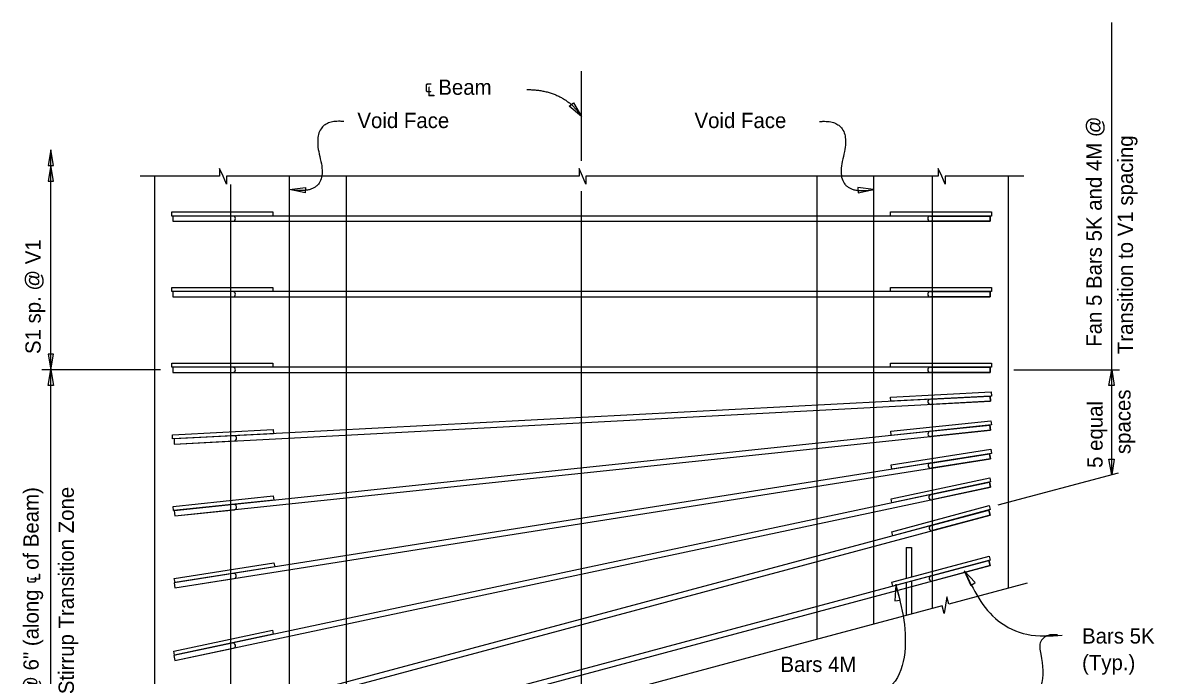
# Model space of a CAD drawing. Extents: x 0.8 to 30.4, y 0.3 to 18.9.
# Drawn here: x 19.16 to 30.38, y 12.43 to 18.91 of the extents above; entities that cross this region are included whole.
import ezdxf

# ---------------------------------------------------------------- set-up
doc = ezdxf.new("R2010")
doc.units = 0
for name, color, linetype in [('BeamConc', 7, 'Continuous'), ('BeamConc_h', 7, 'Continuous'), ('CL_Major', 7, 'Continuous'), ('Dimension', 7, 'Continuous'), ('Rebar', 7, 'Continuous'), ('Rebar_h', 7, 'Continuous'), ('TextStructures', 7, 'Continuous')]:
    doc.layers.add(name, color=color, linetype=linetype)

msp = doc.modelspace()

# ---------------------------------------------------------------- linework, layer by layer
at = {"layer": 'BeamConc'}
for p, q in [((20.473, 11.032), (20.473, 17.385)), ((21.807, 11.389), (21.807, 17.385)), ((27.598, 17.385), (27.598, 12.947)), ((28.932, 17.385), (28.932, 13.298))]:
    msp.add_line(p, q, dxfattribs=at)
at = {"layer": 'BeamConc_h'}
for p, q in [((21.223, 17.303), (21.223, 11.233)), ((22.369, 17.385), (22.369, 11.54)), ((27.036, 17.385), (27.036, 12.79)), ((28.182, 13.097), (28.182, 17.385))]:
    msp.add_line(p, q, dxfattribs=at)
at = {"layer": 'CL_Major'}
for p, q in [((24.702, 17.537), (24.702, 18.427)), ((24.702, 12.302), (24.702, 17.235))]:
    msp.add_line(p, q, dxfattribs=at)
at = {"layer": 'Dimension'}
for p, q in [((29.958, 14.423), (29.958, 18.908)), ((20.527, 15.464), (19.35, 15.464)), ((28.989, 15.464), (30.034, 15.464)), ((30.022, 14.441), (28.83, 14.121))]:
    msp.add_line(p, q, dxfattribs=at)
for points in [[(24.702, 17.978), (24.581, 18.08), (24.621, 18.114)], [(19.442, 17.646), (19.415, 17.49), (19.468, 17.49)], [(19.442, 17.49), (19.415, 17.334), (19.468, 17.334)], [(21.807, 17.252), (21.964, 17.274), (21.962, 17.221)], [(27.598, 17.252), (27.441, 17.274), (27.443, 17.221)], [(19.442, 15.464), (19.468, 15.62), (19.415, 15.62)], [(19.442, 15.464), (19.468, 15.308), (19.415, 15.308)], [(29.958, 15.464), (29.984, 15.308), (29.931, 15.308)], [(29.958, 14.423), (29.931, 14.58), (29.984, 14.58)], [(28.496, 13.47), (28.562, 13.326), (28.606, 13.356)], [(27.817, 13.333), (27.809, 13.175), (27.861, 13.181)]]:
    msp.add_lwpolyline(points, close=True, dxfattribs=at)
for points in [[(19.442, 11.509), (19.442, 17.646)], [(21.694, 17.385), (21.182, 17.385), (21.182, 17.307), (21.148, 17.385), (21.114, 17.462), (21.114, 17.385), (20.325, 17.385)], [(27.522, 17.385), (24.746, 17.385), (24.746, 17.307), (24.712, 17.385), (24.678, 17.462), (24.678, 17.385), (21.694, 17.385)], [(29.086, 17.385), (28.307, 17.385), (28.307, 17.307), (28.273, 17.385), (28.239, 17.462), (28.239, 17.385), (27.522, 17.385)], [(29.121, 13.349), (28.342, 13.141), (28.322, 13.215), (28.31, 13.132), (28.297, 13.048), (28.277, 13.123), (26.782, 12.723)], [(26.782, 12.723), (24.745, 12.177), (24.725, 12.252), (24.713, 12.168), (24.705, 12.116)]]:
    msp.add_lwpolyline(points, dxfattribs=at)
for points in [[(24.159, 18.244), (24.523, 18.244), (24.702, 17.979)], [(22.345, 17.927), (22.008, 17.958), (22.211, 17.182), (21.807, 17.252)], [(27.06, 17.927), (27.397, 17.958), (27.194, 17.182), (27.598, 17.252)]]:
    msp.add_open_spline(points, degree=2, dxfattribs=at)
for points in [[(28.496, 13.47), (28.833, 12.976), (29.118, 12.842), (29.467, 12.833)], [(27.817, 13.338), (27.899, 12.616), (27.755, 12.319), (27.582, 12.253), (27.422, 12.253)], [(29.419, 12.835), (29.343, 12.835), (29.255, 12.772), (29.255, 12.645), (29.255, 12.328), (29.157, 12.174), (29.014, 12.076), (28.873, 12.034), (28.735, 11.996)]]:
    msp.add_spline(points, degree=3, dxfattribs=at)
at = {"layer": 'Rebar'}
for p, q in [((20.64, 17.032), (21.64, 17.032)), ((20.64, 16.99), (20.64, 17.032)), ((21.64, 16.99), (20.64, 16.99)), ((21.245, 16.99), (20.651, 16.99)), ((20.651, 16.99), (20.651, 16.938)), ((21.64, 17.032), (21.64, 16.99)), ((27.765, 17.032), (28.765, 17.032)), ((27.765, 16.99), (27.765, 17.032)), ((28.765, 16.99), (27.765, 16.99)), ((28.16, 16.99), (28.754, 16.99)), ((28.754, 16.99), (28.754, 16.938)), ((28.765, 17.032), (28.765, 16.99)), ((20.651, 16.938), (21.245, 16.938)), ((28.754, 16.938), (28.16, 16.938)), ((20.64, 16.282), (21.64, 16.282)), ((20.64, 16.24), (20.64, 16.282)), ((21.64, 16.282), (21.64, 16.24)), ((27.765, 16.282), (28.765, 16.282)), ((27.765, 16.24), (27.765, 16.282)), ((28.765, 16.282), (28.765, 16.24)), ((21.64, 16.24), (20.64, 16.24)), ((21.245, 16.24), (20.651, 16.24)), ((20.651, 16.24), (20.651, 16.188)), ((20.651, 16.188), (21.245, 16.188)), ((28.765, 16.24), (27.765, 16.24)), ((28.16, 16.24), (28.754, 16.24)), ((28.754, 16.188), (28.16, 16.188)), ((28.754, 16.24), (28.754, 16.188)), ((20.64, 15.532), (21.64, 15.532)), ((20.64, 15.49), (20.64, 15.532)), ((21.64, 15.49), (20.64, 15.49)), ((21.245, 15.49), (20.651, 15.49)), ((20.651, 15.49), (20.651, 15.438)), ((21.64, 15.532), (21.64, 15.49)), ((27.765, 15.532), (28.765, 15.532)), ((27.765, 15.49), (27.765, 15.532)), ((28.765, 15.49), (27.765, 15.49)), ((28.16, 15.49), (28.754, 15.49)), ((28.754, 15.49), (28.754, 15.438)), ((28.765, 15.532), (28.765, 15.49)), ((20.651, 15.438), (21.245, 15.438)), ((28.754, 15.438), (28.16, 15.438)), ((27.765, 15.195), (28.764, 15.247)), ((27.767, 15.153), (27.765, 15.195)), ((28.766, 15.205), (27.767, 15.153)), ((28.16, 15.174), (28.753, 15.205)), ((28.756, 15.153), (28.163, 15.122)), ((28.753, 15.205), (28.756, 15.153)), ((28.764, 15.247), (28.766, 15.205)), ((27.767, 14.856), (28.761, 14.96)), ((28.761, 14.96), (28.766, 14.919)), ((20.646, 14.821), (21.645, 14.873)), ((20.648, 14.779), (20.646, 14.821)), ((21.647, 14.831), (20.648, 14.779)), ((21.256, 14.811), (20.663, 14.78)), ((21.645, 14.873), (21.647, 14.831)), ((27.771, 14.814), (27.767, 14.856)), ((28.766, 14.919), (27.771, 14.814)), ((28.159, 14.855), (28.75, 14.917)), ((28.755, 14.865), (28.165, 14.803)), ((28.75, 14.917), (28.755, 14.865)), ((20.663, 14.78), (20.665, 14.728)), ((20.665, 14.728), (21.259, 14.759)), ((27.771, 14.521), (28.759, 14.677)), ((28.765, 14.636), (27.778, 14.48)), ((28.16, 14.54), (28.747, 14.633)), ((28.747, 14.633), (28.755, 14.582)), ((28.759, 14.677), (28.765, 14.636)), ((27.778, 14.48), (27.771, 14.521)), ((28.755, 14.582), (28.168, 14.489)), ((27.77, 14.186), (28.749, 14.394)), ((28.749, 14.394), (28.757, 14.353)), ((28.757, 14.353), (27.779, 14.145)), ((28.164, 14.227), (28.745, 14.351)), ((28.756, 14.3), (28.175, 14.176)), ((28.745, 14.351), (28.756, 14.3)), ((20.652, 14.109), (21.646, 14.214)), ((21.651, 14.172), (20.656, 14.068)), ((21.646, 14.214), (21.651, 14.172)), ((27.779, 14.145), (27.77, 14.186)), ((20.656, 14.068), (20.652, 14.109)), ((21.254, 14.129), (20.664, 14.067)), ((20.664, 14.067), (20.669, 14.015)), ((20.669, 14.015), (21.26, 14.077)), ((27.777, 13.859), (28.743, 14.118)), ((28.754, 14.078), (27.788, 13.819)), ((28.167, 13.92), (28.741, 14.074)), ((28.741, 14.074), (28.754, 14.024)), ((28.743, 14.118), (28.754, 14.078)), ((28.754, 14.024), (28.18, 13.87)), ((27.788, 13.819), (27.777, 13.859)), ((27.921, 13.703), (27.973, 13.703)), ((27.921, 13.703), (27.921, 13.398)), ((27.973, 13.703), (27.973, 13.412)), ((27.777, 13.359), (28.743, 13.618)), ((28.754, 13.578), (27.788, 13.319)), ((28.743, 13.618), (28.754, 13.578)), ((20.665, 13.396), (21.653, 13.552)), ((21.66, 13.511), (20.672, 13.354)), ((21.653, 13.552), (21.66, 13.511)), ((28.167, 13.42), (28.741, 13.574)), ((28.754, 13.524), (28.18, 13.37)), ((28.741, 13.574), (28.754, 13.524)), ((21.249, 13.446), (20.662, 13.353)), ((20.662, 13.353), (20.671, 13.301)), ((20.672, 13.354), (20.665, 13.396)), ((20.671, 13.301), (21.257, 13.394)), ((27.788, 13.319), (27.777, 13.359)), ((27.921, 13.354), (27.921, 13.028)), ((27.973, 13.368), (27.973, 13.042)), ((20.659, 12.675), (21.638, 12.883)), ((21.646, 12.842), (20.668, 12.634)), ((21.638, 12.883), (21.646, 12.842)), ((21.24, 12.755), (20.659, 12.632)), ((20.67, 12.581), (21.251, 12.704)), ((20.668, 12.634), (20.659, 12.675)), ((20.659, 12.632), (20.67, 12.581))]:
    msp.add_line(p, q, dxfattribs=at)
for centre, start, end in [((21.245, 16.964), 270, 90), ((28.16, 16.964), 90, 270), ((21.245, 16.214), 270, 90), ((28.16, 16.214), 90, 270), ((21.245, 15.464), 270, 90), ((28.16, 15.464), 90, 270), ((28.161, 15.148), 93, 273), ((21.257, 14.785), 273, 93), ((28.162, 14.829), 96, 276), ((28.164, 14.515), 99, 279), ((28.169, 14.202), 102, 282), ((21.257, 14.103), 276, 96), ((28.174, 13.895), 105, 285), ((21.253, 13.42), 279, 99), ((28.174, 13.395), 105, 285), ((21.245, 12.73), 282, 102)]:
    msp.add_arc(centre, 0.026, start, end, dxfattribs=at)
at = {"layer": 'Rebar_h'}
for points in [[(28.754, 16.99), (20.651, 16.99), (20.651, 16.938), (28.754, 16.938)], [(28.754, 16.24), (20.651, 16.24), (20.651, 16.188), (28.754, 16.188)], [(28.754, 15.49), (20.651, 15.49), (20.651, 15.438), (28.754, 15.438)], [(28.753, 15.205), (20.663, 14.78), (20.665, 14.728), (28.756, 15.153)], [(28.75, 14.917), (20.664, 14.067), (20.669, 14.015), (28.755, 14.865)], [(28.747, 14.633), (20.662, 13.353), (20.671, 13.301), (28.755, 14.582)], [(28.745, 14.351), (20.659, 12.632), (20.67, 12.581), (28.756, 14.3)], [(28.741, 14.074), (20.651, 11.906), (20.665, 11.856), (28.754, 14.024)], [(28.741, 13.574), (20.651, 11.406), (20.665, 11.356), (28.754, 13.524)]]:
    msp.add_lwpolyline(points, close=True, dxfattribs=at)

# ---------------------------------------------------------------- texts
at = {"layer": 'Dimension'}
for s, p in [('Bars 5K', (29.664, 12.75)), ('Bars 4M ', (26.674, 12.468)), ('(Typ.)', (29.664, 12.486))]:
    msp.add_text(s, height=0.1512, dxfattribs=at).set_placement(p)
at = {"layer": 'TextStructures'}
for s, p in [('℄ Beam', (23.144, 18.192)), ('Void Face', (22.48, 17.862)), ('Void Face', (25.822, 17.862))]:
    msp.add_text(s, height=0.1512, dxfattribs=at).set_placement(p)
for s, p in [('Fan 5 Bars 5K and 4M @ ', (29.859, 15.693)), ('Transition to V1 spacing', (30.169, 15.62)), ('S1 sp. @ V1 ', (19.34, 15.621)), ('spaces', (30.145, 14.629)), ('5 equal ', (29.868, 14.492)), ('5 sp. @ 6" (along ℄ of Beam)', (19.32, 11.728)), ('Stirrup Transition Zone ', (19.669, 12.248))]:
    msp.add_text(s, height=0.1512, rotation=90, dxfattribs=at).set_placement(p)

doc.saveas('drawing.dxf')
